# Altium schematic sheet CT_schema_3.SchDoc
size 229 x 200 mm
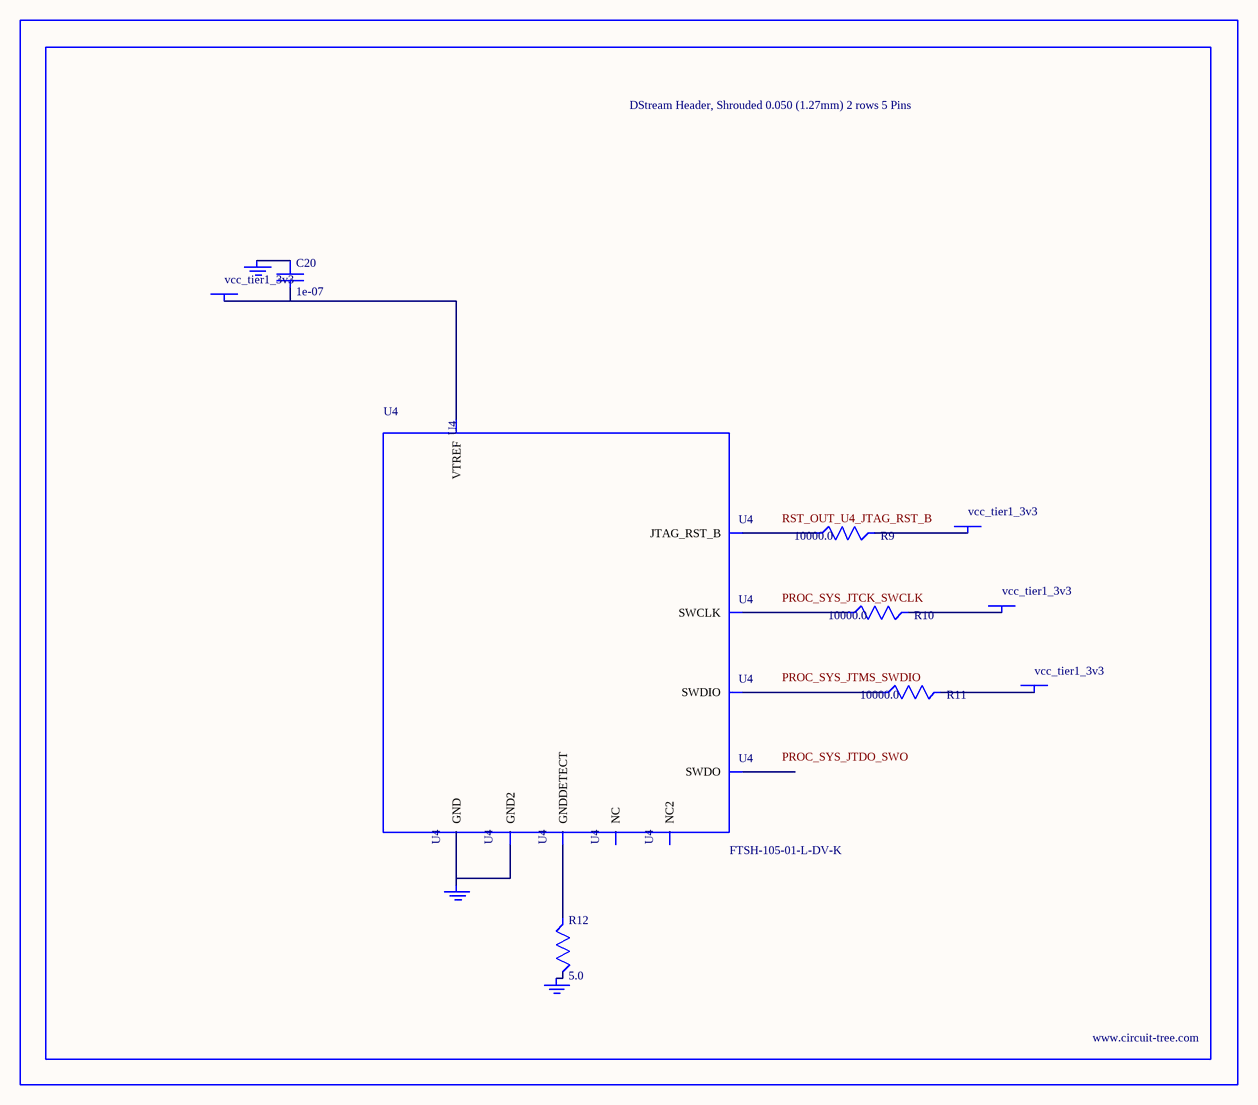
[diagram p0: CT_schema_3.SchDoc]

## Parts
BORDER2  (no value)
C20  1e-07  [C0402]
GND_INSTANCE_2_0  (no value)
GND_INSTANCE_2_1  (no value)
GND_INSTANCE_2_2  (no value)
POWER_INSTANCE_2_0  vcc_tier1_3v3
POWER_INSTANCE_2_1  vcc_tier1_3v3
POWER_INSTANCE_2_2  vcc_tier1_3v3
POWER_INSTANCE_2_3  vcc_tier1_3v3
R9  10000.0  [R0603]
R10  10000.0  [R0603]
R11  10000.0  [R0603]
R12  5.0  [R0603]
U4  FTSH-105-01-L-DV-K  [SAMTEC_FTSH-105-01-L-DV-K]

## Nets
NetC20_1: C20.1 GND_INSTANCE_2_0.0(GND)
NetC20_2: C20.2 POWER_INSTANCE_2_0.0(PWR) U4.1(VTREF)
NetGND_INSTANCE_2_1_0: GND_INSTANCE_2_1.0(GND) R12.2
NetGND_INSTANCE_2_2_0: GND_INSTANCE_2_2.0(GND) U4.3(GND) U4.5(GND2)
NetPOWER_INSTANCE_2_1_0: POWER_INSTANCE_2_1.0(PWR) R11.2
NetPOWER_INSTANCE_2_2_0: POWER_INSTANCE_2_2.0(PWR) R10.2
NetPOWER_INSTANCE_2_3_0: POWER_INSTANCE_2_3.0(PWR) R9.2
NetR9_1: R9.1 U4.10(JTAG_RST_B)
NetR10_1: R10.1 U4.4(SWCLK)
NetR11_1: R11.1 U4.2(SWDIO)
NetR12_1: R12.1 U4.9(GNDDETECT)

Not connected (* = marked no-connect by the designer): U4 6(SWDO) 7(NC) 8(NC2)

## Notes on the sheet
- Labels drawn without touching a wire or pin: PROC_SYS_JTCK_SWCLK, PROC_SYS_JTDO_SWO, PROC_SYS_JTMS_SWDIO, RST_OUT_U4_JTAG_RST_B

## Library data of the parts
BORDER2 = BORDER_PAGE2
C20 = C0402C104K3RACTU
GND_INSTANCE_2_0-GND_INSTANCE_2_2 = GND
POWER_INSTANCE_2_0-POWER_INSTANCE_2_3 = PWR
R9-R11 = RC0603JR-0710KL
R12 = ERJ-3GEYJ5R1V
